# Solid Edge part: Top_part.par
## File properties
Author: Krammer
Template: iso metric part.par
Last saved by: Krammer
Revision: 4
Application: Solid Edge
Accuracy: 0,990
Username: Krammer
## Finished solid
Body 1: solid body, 46 faces, 82 edges, 40 vertices.
  Faces by surface: plane 34, cylinder 11, cone 1
  Edges by curve: line 59, circle 23
Bounding box of the edges (mm): 31.000 x 18.000 x 5.000, from (0, 0, 0) to (31, 18, 5).
Cylindrical faces by radius (mm): R0.75 x9, R6 x1, R9 x1
Conical faces (half-angle, radius in mm at the cone's reference point): 45 deg R8.5 x1
Planar faces by outward normal: +x 3, +y 4, +z 11, -x 3, -y 4, -z 2, oblique 7
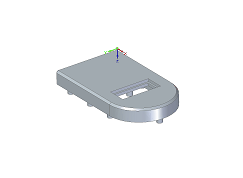
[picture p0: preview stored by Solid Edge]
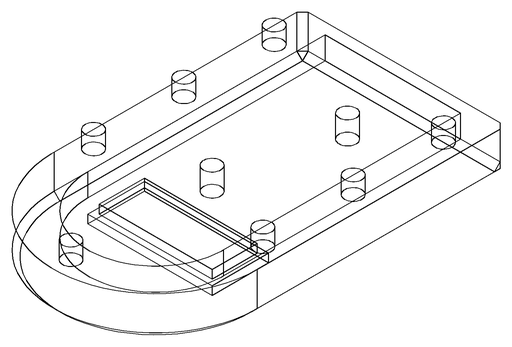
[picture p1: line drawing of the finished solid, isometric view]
